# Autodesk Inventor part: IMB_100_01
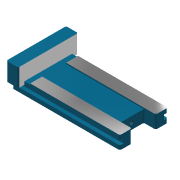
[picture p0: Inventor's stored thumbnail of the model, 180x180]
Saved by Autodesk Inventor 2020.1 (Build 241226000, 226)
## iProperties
Created: 2011-02
Part Number: IMB_100_01
Document SubType Name: Modeling
Designer: F.Stasiak
Density: 1 g/cm^3
Material: Ogólny
Description: Korpus
Appearance: Ciemnobłękitna
Manager: www.cadconsulting.pl
Company: Fabian Stasiak CAD Consulting
Author: F.Stasiak
Subject: Zbiór ćwiczeń. Autodesk Inventor 2020. Kurs podstawowy
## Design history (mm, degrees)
sketch "Szkic1"
  geometry: L1 (-90, -40)-(90, -40); L2 (90, -40)-(90, 40); L3 (90, 40)-(-90, 40); L4 (-90, 40)-(-90, -40); 3 further points
  constraints: 8 end point, 2 midpoint, 2 parallel, 1 horizontal, 1 horizontal alignment, 1 perpendicular, 1 vertical alignment
  dimensions: "d0" = 180 distance of L3.end L2.end; "d1" = 80 distance of L2.end L1.end
extrude "Wyciągnięcie proste1" new body sketch "Szkic1" distance "d2" = 20; taper "d3" = 0 deg
sketch "Szkic2"
  geometry: L1 (-90, -40)-(-90, 40) reference; L2 (-90, 50)-(-70, 50); L3 (-70, 50)-(-70, -50); L4 (-70, -50)-(-90, -50); L5 (-90, -50)-(-90, 50); 2 further points
  constraints: 8 end point, 2 midpoint, 2 parallel, 1 horizontal, 1 perpendicular
  dimensions: "d4" = 20 distance of L3.end L4.end; "d5" = 100 distance of L2.end L3.end
extrude "Wyciągnięcie proste2" join sketch "Szkic2" distance "d6" = 25; taper "d8" = 0 deg; dims "d7" = 5, "d9" = 0
sketch "Szkic3"
  geometry: L1 (90, -40)-(-70, -40) reference; L2 (90, 40)-(90, -40) reference; L3 (-70, 40)-(90, 40) reference; L4 (-60, -40)-(-60, -20); L5 (-60, -20)-(90, -20); L6 (-70, 40)-(-70, -40) reference; 1 further point
  constraints: 4 end point, 2 perpendicular, 2 point on line
  dimensions: "d10" = 20 distance of L4.start L4.end; "d53" = 10 distance between parallel lines of L6 L4
extrude "Wyciągnięcie proste3" join sketch "Szkic3" distance "d12" = 2; taper "d13" = 0 deg
sketch "Szkic4"
  geometry: L1 (0, 0)-(-22, 0) reference; L2 (0, 80)-(-20, 80) reference; L3 (-7, 0)-(-7, 6); L4 (-7, 6)-(-15, 6); L5 (-15, 6)-(-15, 0); L6 (-15, -10)-(-15, 0) reference; 1 further point
  constraints: 6 end point, 3 perpendicular, 2 point on line, 1 collinear
  dimensions: "d14" = 8 distance of L3.end L4.end; "d15" = 6 distance of L3.start L3.end
extrude "Wyciągnięcie proste4" cut sketch "Szkic4" extent not by distance; stored distance "d16" = 3; taper "d17" = 0 deg
mirror "Odbicie lustrzane1"
sketch "Szkic5"
  geometry: L1 (90, 20)-(-60, 20) reference; L2 (-60, -20)-(90, -20) reference; L3 (90, 20)-(90, -20) reference; L4 (70, -20)-(70, 20); 1 further point
  constraints: 2 end point, 2 point on line, 1 perpendicular
  dimensions: "d18" = 20 distance between parallel lines of L4 L3
extrude "Wyciągnięcie proste5" cut sketch "Szkic5" extent not by distance; stored distance "d19" = 3; taper "d20" = 0 deg
hole "Hole1" diameter "d23" = 6.647; stored, may be unused: countersink angle "d27" = 90 deg, drill point angle "d29" = 118 deg; dims "d21" = 10 (= 0.5 x d2), "d22" = 20 (= -d10 + 0.5 x d1), "d24" = 12, "d25" = 4, "d26" = 2, "d28" = 15
chamfer "Faza3" distance "d48" = 2; stored, may be unused: second distance "d49" = 2, angle "d50" = 45 deg
fillet "Zaokrąglenie2" dims "d51" = 2
node "Bryła1"
other parameters: "d44" = 0.5, "d45" = 2, "d46" = -79.25
